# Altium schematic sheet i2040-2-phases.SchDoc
size 431 x 279 mm; Date: Not shown in title block; ApprovedBy: Not shown in title block; CheckedBy: Not shown in title block; Author: Not shown in title block; CompanyName: Not shown in title block; DrawnBy: Mars Leung; Engineer: Mars Leung; Organization: Not shown in title block; Address1: Not shown in title block; Address2: Not shown in title block; Address3: Not shown in title block; Address4: Not shown in title block; DocumentNumber: 1; Revision: 1.0; SheetNumber: 1; SheetTotal: 1; PageSetup: Record=PageOptions|CenterHorizontal=True|CenterVertical=True|PrintScale=0.62|XCorrection=1.00|YCorrection=1.00|PrintKind=0|BorderSize=5000000|LeftOffset=0|BottomOffset=0|Orientation=2|PaperLength=1000|PaperWidth=1000|Scale=100|PaperSource=15|PrintQuality=600|MediaType=1|DitherType=10|PaperKind=Letter|PrintScaleMode=1
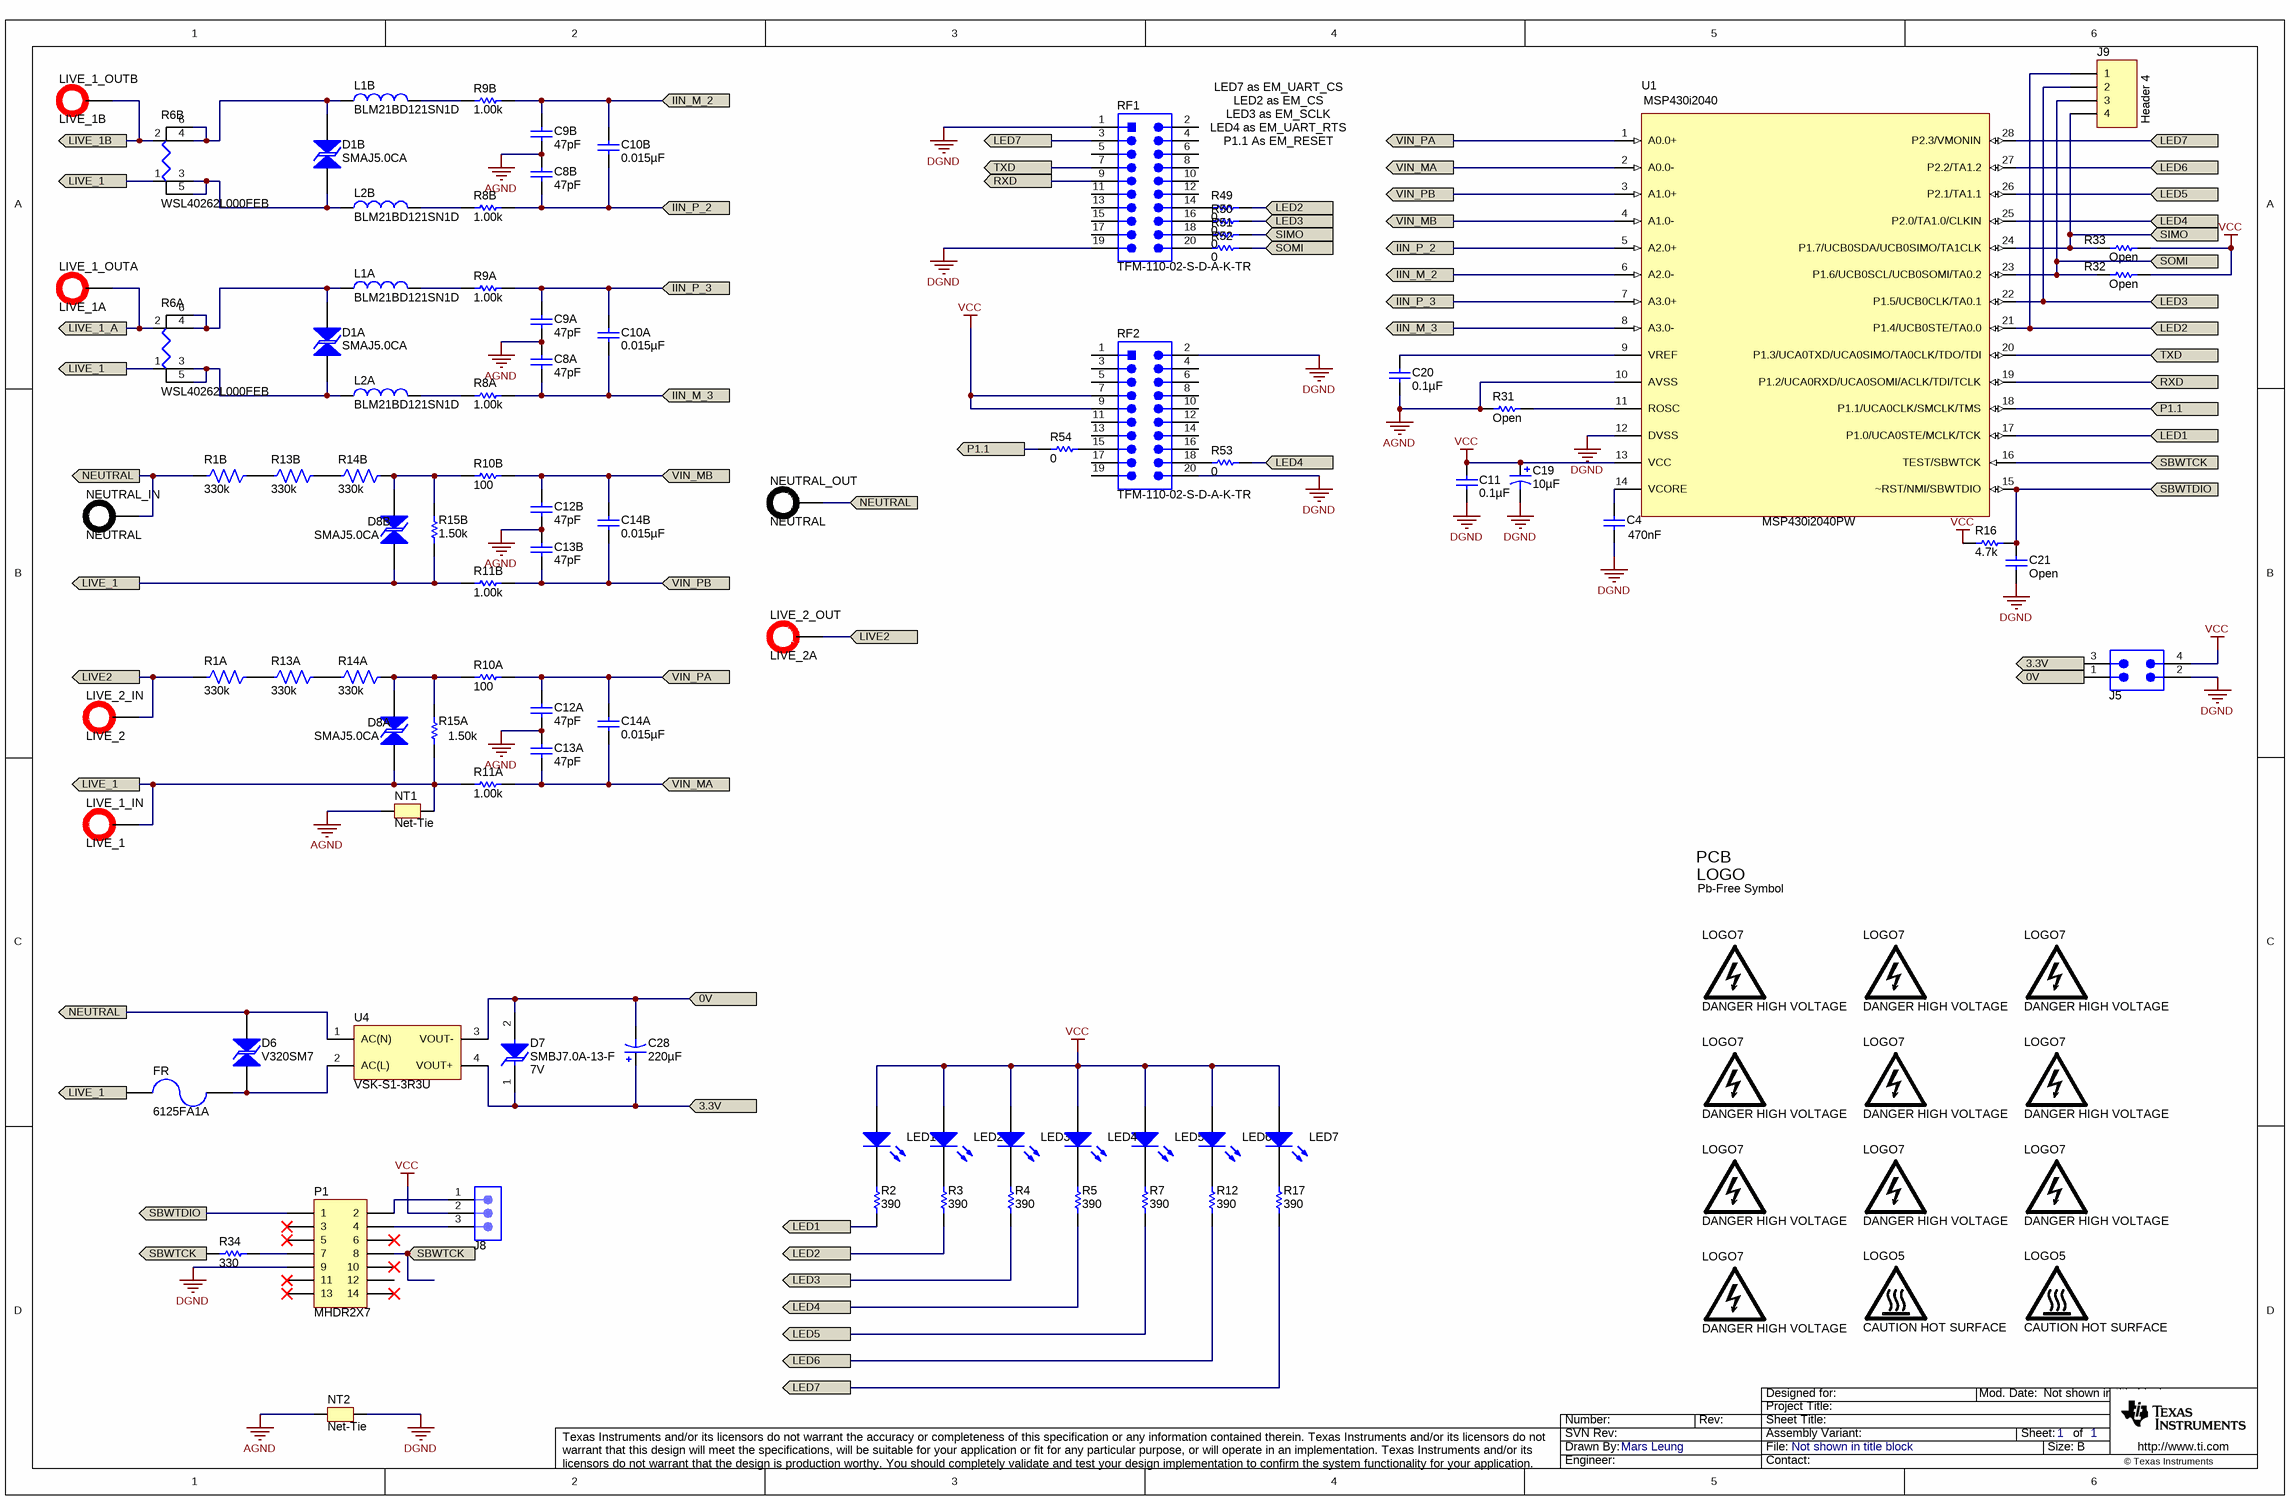
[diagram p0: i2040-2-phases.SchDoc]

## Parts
(Parts that share a designator on the sheet are numbered #1, #2 ... from top to bottom, then left to right.)
C4  470nF  [0603]
C8A  ValueDisplayed: 47pF  [0603]  (hidden comment: 06035A470JAT2A)
C8B  ValueDisplayed: 47pF  [0603]  (hidden comment: 06035A470JAT2A)
C9A  ValueDisplayed: 47pF  [0603]  (hidden comment: 06035A470JAT2A)
C9B  ValueDisplayed: 47pF  [0603]  (hidden comment: 06035A470JAT2A)
C10A  ValueDisplayed: 0.015µF  [0603]  (hidden comment: GRM188R71C153KA01D)
C10B  ValueDisplayed: 0.015µF  [0603]  (hidden comment: GRM188R71C153KA01D)
C11  ValueDisplayed: 0.1µF  [0402]  (hidden comment: 0.1uF)
C12A  ValueDisplayed: 47pF  [0603]  (hidden comment: 06035A470JAT2A)
C12B  ValueDisplayed: 47pF  [0603]  (hidden comment: 06035A470JAT2A)
C13A  ValueDisplayed: 47pF  [0603]  (hidden comment: 06035A470JAT2A)
C13B  ValueDisplayed: 47pF  [0603]  (hidden comment: 06035A470JAT2A)
C14A  ValueDisplayed: 0.015µF  [0603]  (hidden comment: GRM188R71C153KA01D)
C14B  ValueDisplayed: 0.015µF  [0603]  (hidden comment: GRM188R71C153KA01D)
C19  ValueDisplayed: 10µF  [3528-21]  (hidden comment: 293D106X0010B2TE3)
C20  ValueDisplayed: 0.1µF  [0402]  (hidden comment: 0.1uF)
C21  ValueDisplayed: Open  [0603]  (hidden comment: C0603X222K5RACTU)
C28  ValueDisplayed: 220µF  [7343-31]  (hidden comment: 293D227X96R3D2TE3)
D1A  SMAJ5.0CA  [DSO-C2/X1.8]
D1B  SMAJ5.0CA  [DSO-C2/X1.8]
D6  V320SM7  [V320SM7]
D7  SMBJ7.0A-13-F  value 7V  [SMB]
D8A  SMAJ5.0CA  [DSO-C2/X1.8]
D8B  SMAJ5.0CA  [DSO-C2/X1.8]
FR  6125FA1A  [6125FA]
J5  TSW-102-07-G-D  [TSW-102-07-G-D]  (value not drawn)
J8  PBC03SAAN  [PBC03SAAN]  (value not drawn)
J9  Header 4  [HDR1X4]
L1A  BLM21BD121SN1D  [YW0805]
L1B  BLM21BD121SN1D  [YW0805]
L2A  BLM21BD121SN1D  [YW0805]
L2B  BLM21BD121SN1D  [YW0805]
LED1  Used in BOM report  [0805-LED]  (value not drawn)
LED2  Used in BOM report  [0805-LED]  (value not drawn)
LED3  Used in BOM report  [0805-LED]  (value not drawn)
LED4  Used in BOM report  [0805-LED]  (value not drawn)
LED5  Used in BOM report  [0805-LED]  (value not drawn)
LED6  Used in BOM report  [0805-LED]  (value not drawn)
LED7  Used in BOM report  [0805-LED]  (value not drawn)
LIVE_1_IN  LIVE_1  [Hole for Banana Socket]
LIVE_1_OUTA  LIVE_1A  [Hole for Banana Socket]
LIVE_1_OUTB  LIVE_1B  [Hole for Banana Socket]
LIVE_2_IN  LIVE_2  [Hole for Banana Socket]
LIVE_2_OUT  LIVE_2A  [Hole for Banana Socket]
LOGO5#1  CAUTION HOT SURFACE  [IEC_HotSurface_Small]  (no BOM)
LOGO5#2  CAUTION HOT SURFACE  [IEC_HotSurface_Small]  (no BOM)
LOGO7#1  DANGER HIGH VOLTAGE  [IEC_HighVoltage_Small]  (no BOM)
LOGO7#2  DANGER HIGH VOLTAGE  [IEC_HighVoltage_Small]  (no BOM)
LOGO7#3  DANGER HIGH VOLTAGE  [IEC_HighVoltage_Small]  (no BOM)
LOGO7#4  DANGER HIGH VOLTAGE  [IEC_HighVoltage_Small]  (no BOM)
LOGO7#5  DANGER HIGH VOLTAGE  [IEC_HighVoltage_Small]  (no BOM)
LOGO7#6  DANGER HIGH VOLTAGE  [IEC_HighVoltage_Small]  (no BOM)
LOGO7#7  DANGER HIGH VOLTAGE  [IEC_HighVoltage_Small]  (no BOM)
LOGO7#8  DANGER HIGH VOLTAGE  [IEC_HighVoltage_Small]  (no BOM)
LOGO7#9  DANGER HIGH VOLTAGE  [IEC_HighVoltage_Small]  (no BOM)
LOGO7#10  DANGER HIGH VOLTAGE  [IEC_HighVoltage_Small]  (no BOM)
Logo?  Pb-Free Symbol  [Pb-Free_Overlay_Medium]  (no BOM)
NEUTRAL_IN  NEUTRAL  [Hole for Banana Socket]
NEUTRAL_OUT  NEUTRAL  [Hole for Banana Socket]
NT1  Net-Tie  [Net-Tie_10mil]  (net tie, no BOM)
NT2  Net-Tie  [Net-Tie_20milWide_60milLong]  (net tie, no BOM)
P1  MHDR2X7  [2X7BOXHEADER]
R1A  330k  [R2512]
R1B  330k  [R2512]
R2  390  [0603]
R3  390  [0603]
R4  390  [0603]
R5  390  [0603]
R6A  WSL40262L000FEB  [Current Sensing Pad]
R6B  WSL40262L000FEB  [Current Sensing Pad]
R7  390  [0603]
R8A  1.00k  [0603]
R8B  1.00k  [0603]
R9A  1.00k  [0603]
R9B  1.00k  [0603]
R10A  100  [0603]
R10B  100  [0603]
R11A  1.00k  [0603]
R11B  1.00k  [0603]
R12  390  [0603]
R13A  330k  [R2512]
R13B  330k  [R2512]
R14A  330k  [R2512]
R14B  330k  [R2512]
R15A  1.50k  [0805]
R15B  1.50k  [0805]
R16  4.7k  [0603]
R17  390  [0603]
R31  Open  [0603]
R32  Open  [0603]
R33  Open  [0603]
R34  330  [0603]
R49  0  [0603]
R50  0  [0603]
R51  0  [0603]
R52  0  [0603]
R53  0  [0603]
R54  0  [0603]
RF1  TFM-110-02-S-D-A-K-TR  [Samtec_TFM-110-02-S-D-A-K]
RF2  TFM-110-02-S-D-A-K-TR  [Samtec_TFM-110-02-S-D-A-K]
U1  MSP430i2040PW  [TSSO10x6-G28]
U4  VSK-S1-3R3U  [VSK-S1]

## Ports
0V, 3.3V, IIN_M_2, IIN_M_3, IIN_P_2, IIN_P_3, LED1, LED2, LED3, LED4, LED5, LED6, LED7, LIVE2, LIVE_1, LIVE_1_A, LIVE_1B, NEUTRAL, P1.1, RXD, SBWTCK, SBWTDIO, SIMO, SOMI, TXD, VIN_MA, VIN_MB, VIN_PA, VIN_PB

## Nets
AGND: C8A.1 C8B.1 C9A.2 C9B.2 C12A.2 C12B.2 C13A.1 C13B.1 C20.2 NT1.1 NT2.1 R31.1 U1.10(AVSS)
DGND: C4.2 C11.2 C19.2(-) C21.2 J5.2 NT2.2 P1.9 RF1.1 RF1.19 RF2.2 RF2.20 U1.12(DVSS)
VCC: C11.1 C19.1(+) J5.4 J8.2 LED1.1(A) LED2.1(A) LED3.1(A) LED4.1(A) LED5.1(A) LED6.1(A) LED7.1(A) R16.1 R32.2 R33.2 RF2.7 RF2.9 U1.13(VCC)
0V: C28.2(-) D7.2(A) J5.1 U4.3(VOUT-) ; port 0V
3.3V: C28.1(+) D7.1(K) J5.3 U4.4(VOUT+) ; port 3.3V
IIN_M_2: C9B.1 C10B.1 R9B.2 U1.6(A2.0-) ; port IIN_M_2
IIN_M_3: C8A.2 C10A.2 R8A.2 U1.8(A3.0-) ; port IIN_M_3
IIN_P_2: C8B.2 C10B.2 R8B.2 U1.5(A2.0+) ; port IIN_P_2
IIN_P_3: C9A.1 C10A.1 R9A.2 U1.7(A3.0+) ; port IIN_P_3
LED1: R2.1 U1.17(P1.0/UCA0STE/MCLK/TCK) ; port LED1
LED2: J9.1 R3.1 R49.2 U1.21(P1.4/UCB0STE/TA0.0) ; port LED2
LED3: J9.2 R4.1 R50.2 U1.22(P1.5/UCB0CLK/TA0.1) ; port LED3
LED4: R5.1 R53.2 U1.25(P2.0/TA1.0/CLKIN) ; port LED4
LED5: R7.1 U1.26(P2.1/TA1.1) ; port LED5
LED6: R12.1 U1.27(P2.2/TA1.2) ; port LED6
LED7: R17.1 RF1.3 U1.28(P2.3/VMONIN) ; port LED7
LIVE2: LIVE_2_IN.1 LIVE_2_OUT.1 R1A.1 ; port LIVE2
LIVE_1: D8A.1 D8B.1 FR.2 LIVE_1_IN.1 NT1.2 R6A.1 R6B.1 R11A.1 R11B.1 R15A.1 R15B.1 ; port LIVE_1
LIVE_1_A: LIVE_1_OUTA.1 R6A.2 ; port LIVE_1_A
LIVE_1B: LIVE_1_OUTB.1 R6B.2 ; port LIVE_1B
NEUTRAL: D6.2 NEUTRAL_IN.1 NEUTRAL_OUT.1 R1B.1 U4.1(AC(N)) ; port NEUTRAL
P1.1: R54.1 U1.18(P1.1/UCA0CLK/SMCLK/TMS) ; port P1.1
RXD: RF1.9 U1.19(P1.2/UCA0RXD/UCA0SOMI/ACLK/TDI/TCLK) ; port RXD
SBWTCK: P1.8 R34.1 U1.16(TEST/SBWTCK) ; port SBWTCK
SBWTDIO: C21.1 P1.1 R16.2 U1.15(~RST/NMI/SBWTDIO) ; port SBWTDIO
SIMO: J9.4 R33.1 R51.2 U1.24(P1.7/UCB0SDA/UCB0SIMO/TA1CLK) ; port SIMO
SOMI: J9.3 R32.1 R52.2 U1.23(P1.6/UCB0SCL/UCB0SOMI/TA0.2) ; port SOMI
TXD: RF1.7 U1.20(P1.3/UCA0TXD/UCA0SIMO/TA0CLK/TDO/TDI) ; port TXD
VIN_MA: C13A.2 C14A.2 R11A.2 U1.2(A0.0-) ; port VIN_MA
VIN_MB: C12B.1 C14B.1 R10B.2 U1.4(A1.0-) ; port VIN_MB
VIN_PA: C12A.1 C14A.1 R10A.2 U1.1(A0.0+) ; port VIN_PA
VIN_PB: C13B.2 C14B.2 R11B.2 U1.3(A1.0+) ; port VIN_PB
NetC4_1: C4.1 U1.14(VCORE)
NetC20_1: C20.1 U1.9(VREF)
NetD1A_1: D1A.1 L2A.1 R6A.3 R6A.5
NetD1A_2: D1A.2 L1A.1 R6A.4 R6A.6
NetD1B_1: D1B.1 L2B.1 R6B.3 R6B.5
NetD1B_2: D1B.2 L1B.1 R6B.4 R6B.6
NetD6_1: D6.1 FR.1 U4.2(AC(L))
NetD8A_2: D8A.2 R10A.1 R14A.2 R15A.2
NetD8B_2: D8B.2 R10B.1 R14B.2 R15B.2
NetJ8_1: J8.1 P1.2
NetJ8_3: J8.3 P1.4
NetL1A_2: L1A.2 R9A.1
NetL1B_2: L1B.2 R9B.1
NetL2A_2: L2A.2 R8A.1
NetL2B_2: L2B.2 R8B.1
NetLED1_2: LED1.2(K) R2.2
NetLED2_2: LED2.2(K) R3.2
NetLED3_2: LED3.2(K) R4.2
NetLED4_2: LED4.2(K) R5.2
NetLED5_2: LED5.2(K) R7.2
NetLED6_2: LED6.2(K) R12.2
NetLED7_2: LED7.2(K) R17.2
NetP1_7: P1.7 R34.2
NetR1A_2: R1A.2 R13A.1
NetR1B_2: R1B.2 R13B.1
NetR13A_2: R13A.2 R14A.1
NetR13B_2: R13B.2 R14B.1
NetR31_2: R31.2 U1.11(ROSC)
NetR49_1: R49.1 RF1.14
NetR50_1: R50.1 RF1.16
NetR51_1: R51.1 RF1.18
NetR52_1: R52.1 RF1.20
NetR53_1: R53.1 RF2.18
NetR54_2: R54.2 RF2.15

Not connected (* = marked no-connect by the designer): P1 3* 5* 6* 10* 11* 12 13* 14*; RF1 2 4 5 6 8 10 11 12 13 15 17; RF2 1 3 4 5 6 8 10 11 12 13 14 16 17 19

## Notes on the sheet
- LED7 as EM_UART_CS
- LED2 as EM_CS
- LED3 as EM_SCLK
- LED4 as EM_UART_RTS
- P1.1 As EM_RESET

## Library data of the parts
C4 = Capacitor: CAP, CERM, 470nF, 16V, [TempCo], xx%, [PackageReference]; Manufacturer: Used in BOM report; PartNumber: EMK107F474ZA-T; Polarized: N; U/M: EA
C8A C8B C9A C9B C12A C12B C13A C13B = 06035A470JAT2A: CAP, CERM, 47pF, 50V, +/-5%, C0G/NP0, 0603; Manufacturer: AVX; Polarized: N; CompType: Capacitor; U/M: EA; Cap_F: 0.000000000047; Tolerance_%: 5; ESR_Ohm: 0.174; Value1: 0.174 ohm; VDC_V: 50; TaMin_C: -55; TaMax_C: 125
C10A C10B C14A C14B = GRM188R71C153KA01D: CAP, CERM, 0.015uF, 16V, +/-10%, X7R, 0603; Manufacturer: MuRata; Polarized: N; CompType: Capacitor; U/M: EA; Cap_F: 0.000000015; Tolerance_%: 10; Value1: Unknown; VDC_V: 16; TaMin_C: -55; TaMax_C: 125
C11 C20 = C1005X5R1A104K: CAP, CERM, 0.1uF, 10V, +/-10%, X5R, 0402; Manufacturer: TDK; Polarized: N; CompType: Capacitor; U/M: EA; Cap_F: 0.0000001; Tolerance_%: 10; ESR_Ohm: 0.0186; Value1: 0.0186 ohm; TaMin_C: -55; TaMax_C: 85
C19 = 293D106X0010B2TE3: CAP, TANT, 10uF, 10V, +/-20%, 2.5 ohm, 3528-21 SMD; Manufacturer: Vishay-Sprague; Polarized: Y; CompType: Capacitor; U/M: EA; Cap_F: 0.00001; Tolerance_%: 20; Value1: 2.5 ohm; VDC_V: 10; ESR_Ohm: 2.5; IRMS_A: 0.18; TaMin_C: -55; TaMax_C: 125; Cap_Case: B
C21 = C0603X222K5RACTU: CAP, CERM, 2200pF, 50V, +/-10%, X7R, 0603; Manufacturer: Kemet; Polarized: N; CompType: Capacitor; U/M: EA; Cap_F: 0.0000000022; Tolerance_%: 10; Value1: Unknown; VDC_V: 50; TaMin_C: -55; TaMax_C: 125
C28 = 293D227X96R3D2TE3: CAP, TANT, 220uF, 6.3V, +/-10%, 0.6 ohm, 7343-31 SMD; Manufacturer: Vishay-Sprague; Polarized: Y; CompType: Capacitor; U/M: EA; Cap_F: 0.00022; Tolerance_%: 10; Value1: 0.6 ohm; VDC_V: 6.3; ESR_Ohm: 0.6; IRMS_A: 0.5; TaMin_C: -55; TaMax_C: 125; Cap_Case: D
D1A D1B D8A D8B = SMAJ5.0CA: Manufacturer: Littelfuse Inc; SymbolVersion: use current date i.e. 2008-05-20; SymbolCreator: Use LDAP id; CompType: Used in some BOM reports.  Useful for finding later.; U/M: EA, IN, or GM
D6 = V320SM7: Manufacturer: Littelfuse Inc; SymbolVersion: use current date i.e. 2008-05-20; SymbolCreator: Use LDAP id; CompType: Used in some BOM reports.  Useful for finding later.; U/M: EA, IN, or GM
D7 = SMBJ7.0A-13-F: Diode, TVS, Uni, 7V, 600W, SMB; Manufacturer: Diodes Inc.; U/M: EA; Power_W: 5; Vr_V: 7; Value1: 5W
FR = 6125FA1A: Fuse, 1A,125V, SMD; Manufacturer: Cooper Bussman; Alternate Manufacturer: Any; Alternate PartNumber: Equivalent; U/M: EA; OpeningTime_100%_min: 4; OpeningTime_200%_max: 5; VDC_V: 125; Interrupt_DC: 300; Interrupt_AC: 50; Irating_A: 1; Rtyp_Ohm: 0.11; MeltingTyp: 0.14; Vdrop: 0.17; Soldering_Wave_MaxTemp_C: 260; Soldering_Wave_MaxTime_s: 10; Soldering_Reflow_MaxTime_s: 30
J5 = TSW-102-07-G-D: Header, TH, 100mil, 2x2, Gold plated, 230 mil above insulator; Manufacturer: Samtec, Inc.; Alternate Manufacturer: Any; Alternate PartNumber: Equivalent; U/M: EA
J8 = PBC03SAAN: Header, TH, 100mil, 1x3, Gold plated, 230 mil above insulator; Manufacturer: Sullins Connector Solutions; Alternate Manufacturer: Any; Alternate PartNumber: Equivalent; U/M: EA
J9 = Header 4: Header, 4-Pin
L1A L1B L2A L2B = Inductor: Inductor, FERRITE CHIP 120 OHM 0805; Manufacturer: Murata Electronics; U/M: EA
LED1 LED5 = LED-0805: Red; SymbolVersion: use current date i.e. 2008-05-20; SymbolCreator: Use LDAP id; CompType: Used in some BOM reports.  Useful for finding later.; U/M: EA, IN, or GM
LED2 LED6 = LED-0805: Green; SymbolVersion: use current date i.e. 2008-05-20; SymbolCreator: Use LDAP id; CompType: Used in some BOM reports.  Useful for finding later.; U/M: EA, IN, or GM
LED3 LED7 = LED-0805: Blue; SymbolVersion: use current date i.e. 2008-05-20; SymbolCreator: Use LDAP id; CompType: Used in some BOM reports.  Useful for finding later.; U/M: EA, IN, or GM
LED4 = LED-0805: White; SymbolVersion: use current date i.e. 2008-05-20; SymbolCreator: Use LDAP id; CompType: Used in some BOM reports.  Useful for finding later.; U/M: EA, IN, or GM
LIVE_1_IN LIVE_1_OUTA LIVE_1_OUTB LIVE_2_IN LIVE_2_OUT = Hole for Banana Socket (Red): Manufacturer: Used in BOM report; SymbolVersion: use current date i.e. 2008-05-20; SymbolCreator: Use LDAP id; CompType: Used in some BOM reports.  Useful for finding later.; U/M: EA, IN, or GM
LOGO5#1 LOGO5#2 = IEC_HotSurface: IEC 61010-1 Hot Surface Warning; SymbolCreator: a0412235
LOGO7#1-LOGO7#10 = IEC_HighVoltage: IEC 61010-1 High Voltage Warning; SymbolCreator: a0412235
Logo? = Pb-Free: SymbolCreator: a0412235
NEUTRAL_IN NEUTRAL_OUT = Hole for Banana Socket (Black): Manufacturer: Used in BOM report; SymbolVersion: use current date i.e. 2008-05-20; SymbolCreator: Use LDAP id; CompType: Used in some BOM reports.  Useful for finding later.; U/M: EA, IN, or GM
NT1 NT2 = Net-Tie: Single point connection between nets.; SymbolCreator: codlsc
P1 = MHDR2X7: Header, 7-Pin, Dual row
R1A R1B R13A R13B R14A R14B = R2512: Resistor, 330kOhm, 1W, 1%; Manufacturer: Vishay Dale; PartNumber: CRCW2512330KFKEG; Area: 35100
R2-R5 R7 R12 R17 = RC0603JR-07390RL: RES, 390 ohm, 5%, 0.1W, 0603; Manufacturer: Yageo America; CompType: Resistor; Value_Code: 390R; Tolerance_%: 5; Power_W: 0.1; VDC_V: 50; TempCo: 100 ppm/C; EIA_Code: E24; U/M: EA
R6A R6B = ULRB12512R0005FLFSLT: Shunt Resistor; Manufacturer: Vishay Dale; SymbolVersion: use current date i.e. 2008-05-20; SymbolCreator: Use LDAP id; CompType: Used in some BOM reports.  Useful for finding later.; U/M: EA, IN, or GM
R8A R8B R9A R9B R11A R11B = CRCW06031K00FKEA: RES, 1.00k ohm, 1%, 0.1W, 0603; Manufacturer: Vishay-Dale; CompType: Resistor; Res_ohm: 1000; Value_Code: 1k00; Tolerance_%: 1; Power_W: 0.1; VDC_V: 75; TempCo: 100 ppm/C; EIA_Code: E96; U/M: EA
R10A R10B = CRCW0603100RFKEA: RES, 100 ohm, 1%, 0.1W, 0603; Manufacturer: Vishay-Dale; CompType: Resistor; Value_Code: 100R; Tolerance_%: 1; Power_W: 0.1; VDC_V: 75; TempCo: 100 ppm/C; EIA_Code: E96; U/M: EA
R15A R15B = CRCW08051K50FKEA: RES, 1.50k ohm, 1%, 0.125W, 0805; Manufacturer: Vishay-Dale; CompType: Resistor; Res_ohm: 1500; Value_Code: 1k50; Tolerance_%: 1; Power_W: 0.125; VDC_V: 150; TempCo: 100 ppm/C; EIA_Code: E96; U/M: EA
R16 = CRCW06034K70JNEA: RES, 4.7k ohm, 5%, 0.1W, 0603; Manufacturer: Vishay-Dale; CompType: Resistor; Res_ohm: 4700; Value_Code: 4k70; Tolerance_%: 5; Power_W: 0.1; VDC_V: 75; TempCo: 200 ppm/C; EIA_Code: E24; U/M: EA
R31 = Resistor: RES, Open ohm, x%, xW, 0603; Manufacturer: Used in BOM report; U/M: EA
R32 R33 = Resistor: RES, xxx ohm, x%, xW, [PackageReference]; Manufacturer: Used in BOM report; U/M: EA
R34 = CRCW0603330RJNEA: RES, 330 ohm, 5%, 0.1W, 0603; Manufacturer: Vishay-Dale; CompType: Resistor; U/M: EA; Value_Code: 330R; Tolerance_%: 5; Power_W: 0.1; VDC_V: 75; TempCo: 200 ppm/C; EIA_Code: E24
R49-R54 = CRCW06030000Z0EA: RES, 0 ohm, 5%, 0.1W, 0603; Manufacturer: Vishay-Dale; CompType: Resistor; Value_Code: 0000; Tolerance_%: 5; Power_W: 0.1; VDC_V: 75; TempCo: 200 ppm/C; EIA_Code: E24; U/M: EA
RF1 RF2 = TFM-110-02-S-D-A-K-TR: CONN SHRD HDR HDR 20 POS 1.27MM SLDR ST SMD; Manufacturer: Samtec; SymbolCreator: a0412235; CompType: Header; U/M: EA
U1 = MSP430i2040: Manufacturer: Texas Instruments; SymbolVersion: use current date i.e. 2008-05-20; SymbolCreator: Use LDAP id; CompType: Used in some BOM reports.  Useful for finding later.; U/M: EA, IN, or GM
U4 = VSK-S1: On board block power suppply; Manufacturer: CUN Inc; SymbolVersion: use current date i.e. 2008-05-20; SymbolCreator: Use LDAP id; CompType: Power Supply; U/M: EA, IN, or GM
